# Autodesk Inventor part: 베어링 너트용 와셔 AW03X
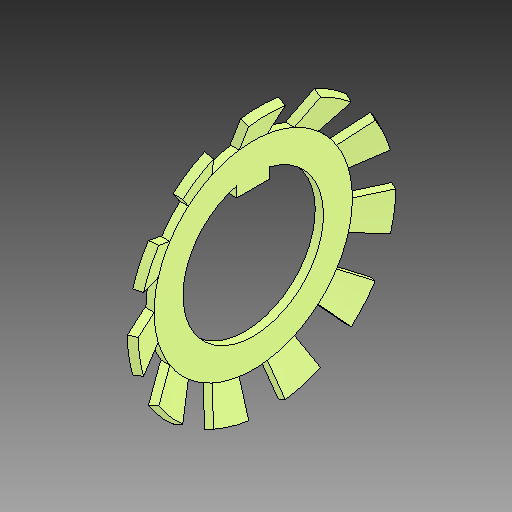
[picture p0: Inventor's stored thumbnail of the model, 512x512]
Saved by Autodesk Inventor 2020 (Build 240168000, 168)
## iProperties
Created: 2025-03
Part Number: 베어링 너트용 와셔 AW03X
Material: 강철, 연강
Description: 잠금 와셔
Document SubType Name: Modeling
Designer: CA01
Density: 7.85 g/cm^3
Appearance: 기본값
Author: jhkim
Sending System: Autodesk Inventor 2025
Preprocessor: ST-DEVELOPER v20
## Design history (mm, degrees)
feature "Solid1"
node "솔리드1"
